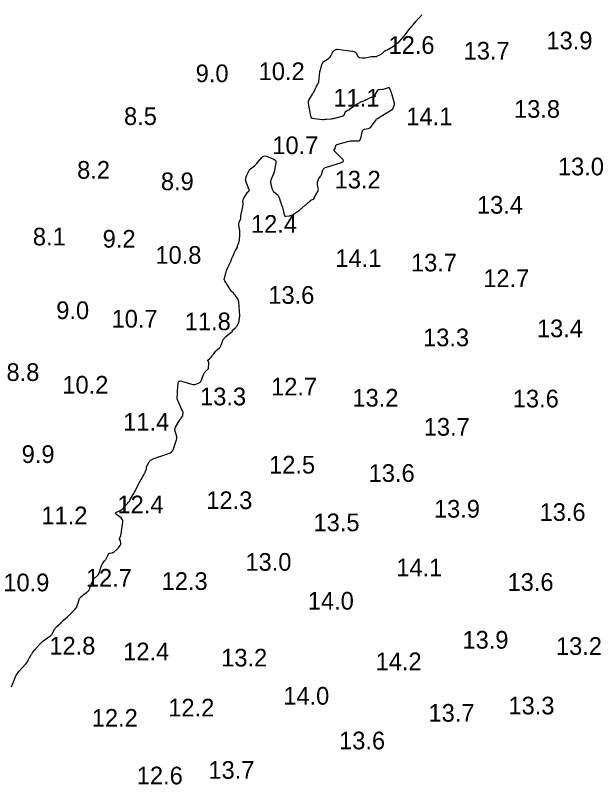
# Model space of a CAD drawing. Extents: x 815352 to 820877, y 582403 to 597439.
# Drawn here: x 820293.3 to 820456.5, y 589480.6 to 589698.1 of the extents above; entities that cross this region are included whole.
import ezdxf

# ---------------------------------------------------------------- set-up
doc = ezdxf.new("R2010")
doc.units = 0
doc.layers.add('V-CONT-EL12', color=7, linetype='Continuous')
doc.layers.add('V-TOPO-SOUN', color=7, linetype='Continuous')

msp = doc.modelspace()

# ---------------------------------------------------------------- linework, layer by layer
at = {"layer": 'V-CONT-EL12'}
msp.add_lwpolyline([(820292.15, 589508.3), (820293.31, 589511.15), (820293.5, 589511.58), (820293.73, 589511.98), (820294, 589512.36), (820294.31, 589512.72), (820296.14, 589514.7), (820296.19, 589514.75), (820296.24, 589514.8), (820296.28, 589514.86), (820296.33, 589514.91), (820296.5, 589515.13), (820296.54, 589515.19), (820296.58, 589515.25), (820296.61, 589515.31), (820296.64, 589515.37), (820296.94, 589516.02), (820297, 589516.14), (820297.07, 589516.27), (820297.14, 589516.39), (820297.21, 589516.52), (820297.73, 589517.36), (820297.85, 589517.54), (820297.97, 589517.72), (820298.09, 589517.89), (820298.22, 589518.06), (820298.77, 589518.77), (820298.91, 589518.94), (820299.05, 589519.11), (820299.19, 589519.28), (820299.34, 589519.44), (820300.16, 589520.35), (820300.23, 589520.42), (820300.3, 589520.49), (820300.37, 589520.56), (820300.45, 589520.63), (820300.74, 589520.91), (820300.82, 589520.98), (820300.89, 589521.04), (820300.97, 589521.1), (820301.05, 589521.16), (820303.03, 589522.58), (820303.25, 589522.76), (820303.45, 589522.96), (820303.62, 589523.19), (820303.77, 589523.44), (820304.4, 589524.66), (820304.49, 589524.82), (820304.59, 589524.96), (820304.71, 589525.1), (820304.84, 589525.23), (820305.52, 589525.83), (820305.59, 589525.89), (820305.66, 589525.95), (820305.73, 589526.01), (820305.8, 589526.07), (820306.08, 589526.31), (820306.15, 589526.37), (820306.22, 589526.43), (820306.28, 589526.49), (820306.34, 589526.56), (820306.6, 589526.84), (820306.66, 589526.91), (820306.72, 589526.98), (820306.79, 589527.04), (820306.86, 589527.11), (820307.97, 589528.11), (820308.17, 589528.29), (820308.38, 589528.48), (820308.58, 589528.68), (820308.78, 589528.87), (820309.83, 589529.91), (820309.9, 589529.98), (820309.96, 589530.05), (820310.03, 589530.12), (820310.09, 589530.19), (820310.39, 589530.52), (820310.42, 589530.57), (820310.46, 589530.62), (820310.49, 589530.67), (820310.52, 589530.72), (820310.62, 589530.93), (820310.64, 589530.99), (820310.66, 589531.04), (820310.68, 589531.1), (820310.7, 589531.15), (820311.41, 589533.23), (820311.47, 589533.37), (820311.55, 589533.5), (820311.64, 589533.62), (820311.75, 589533.72), (820312.23, 589534.1), (820312.35, 589534.2), (820312.47, 589534.29), (820312.6, 589534.39), (820312.72, 589534.48), (820313.33, 589534.93), (820313.4, 589534.99), (820313.48, 589535.05), (820313.55, 589535.11), (820313.62, 589535.17), (820313.9, 589535.43), (820313.97, 589535.5), (820314.03, 589535.57), (820314.07, 589535.65), (820314.11, 589535.73), (820314.27, 589536.13), (820314.31, 589536.22), (820314.35, 589536.32), (820314.39, 589536.41), (820314.42, 589536.51), (820315.02, 589538.11), (820315.13, 589538.36), (820315.27, 589538.6), (820315.44, 589538.82), (820315.64, 589539.02), (820316.49, 589539.77), (820316.69, 589539.97), (820316.85, 589540.19), (820316.98, 589540.43), (820317.08, 589540.7), (820317.65, 589542.63), (820317.71, 589542.81), (820317.79, 589542.98), (820317.89, 589543.14), (820318, 589543.29), (820318.5, 589543.89), (820318.61, 589544.03), (820318.71, 589544.17), (820318.81, 589544.33), (820318.89, 589544.48), (820319.32, 589545.27), (820319.36, 589545.35), (820319.4, 589545.43), (820319.44, 589545.51), (820319.48, 589545.59), (820319.63, 589545.92), (820319.67, 589545.99), (820319.73, 589546.05), (820319.8, 589546.08), (820319.88, 589546.1), (820320.56, 589546.18), (820320.7, 589546.21), (820320.83, 589546.25), (820320.95, 589546.32), (820321.07, 589546.4), (820321.95, 589547.15), (820322.09, 589547.27), (820322.21, 589547.4), (820322.34, 589547.53), (820322.45, 589547.66), (820322.95, 589548.29), (820323.03, 589548.41), (820323.07, 589548.52), (820323.09, 589548.65), (820323.09, 589548.78), (820322.99, 589549.46), (820322.97, 589549.53), (820322.95, 589549.6), (820322.92, 589549.67), (820322.89, 589549.74), (820322.73, 589550), (820322.7, 589550.06), (820322.69, 589550.13), (820322.7, 589550.2), (820322.72, 589550.26), (820322.95, 589550.68), (820323, 589550.77), (820323.04, 589550.87), (820323.07, 589550.97), (820323.09, 589551.07), (820323.22, 589551.73), (820323.24, 589551.88), (820323.27, 589552.02), (820323.29, 589552.17), (820323.31, 589552.32), (820323.64, 589554.86), (820323.64, 589555.22), (820323.56, 589555.54), (820323.39, 589555.82), (820323.13, 589556.06), (820321.84, 589557.02), (820321.65, 589557.2), (820321.59, 589557.38), (820321.67, 589557.54), (820321.89, 589557.69), (820323.04, 589558.26), (820323.32, 589558.42), (820323.58, 589558.6), (820323.82, 589558.81), (820324.04, 589559.04), (820324.97, 589560.1), (820325.19, 589560.37), (820325.39, 589560.64), (820325.58, 589560.92), (820325.76, 589561.22), (820326.56, 589562.65), (820326.73, 589562.95), (820326.89, 589563.24), (820327.05, 589563.54), (820327.21, 589563.84), (820327.83, 589565.04), (820327.99, 589565.34), (820328.15, 589565.64), (820328.31, 589565.93), (820328.47, 589566.23), (820329.7, 589568.41), (820329.78, 589568.56), (820329.86, 589568.71), (820329.93, 589568.86), (820329.99, 589569.02), (820330.27, 589569.77), (820330.3, 589569.87), (820330.33, 589569.97), (820330.35, 589570.08), (820330.37, 589570.18), (820330.44, 589570.61), (820330.46, 589570.71), (820330.49, 589570.81), (820330.53, 589570.91), (820330.58, 589571.01), (820331.08, 589571.86), (820331.17, 589572), (820331.29, 589572.13), (820331.42, 589572.25), (820331.57, 589572.34), (820332.26, 589572.73), (820332.38, 589572.8), (820332.51, 589572.86), (820332.64, 589572.91), (820332.78, 589572.96), (820333.32, 589573.14), (820333.45, 589573.19), (820333.59, 589573.23), (820333.72, 589573.28), (820333.86, 589573.32), (820337.15, 589574.47), (820337.23, 589574.5), (820337.31, 589574.55), (820337.38, 589574.61), (820337.44, 589574.69), (820337.67, 589574.99), (820337.73, 589575.07), (820337.78, 589575.16), (820337.82, 589575.24), (820337.85, 589575.33), (820338.8, 589578.09), (820338.83, 589578.16), (820338.85, 589578.24), (820338.87, 589578.32), (820338.88, 589578.39), (820338.94, 589578.71), (820338.95, 589578.79), (820338.95, 589578.87), (820338.94, 589578.94), (820338.92, 589579.02), (820338.43, 589580.61), (820338.37, 589580.9), (820338.37, 589581.18), (820338.44, 589581.45), (820338.56, 589581.71), (820339.79, 589583.74), (820339.87, 589583.87), (820339.95, 589584), (820340.03, 589584.13), (820340.12, 589584.25), (820340.52, 589584.83), (820340.57, 589584.92), (820340.61, 589585.02), (820340.64, 589585.12), (820340.66, 589585.23), (820340.7, 589585.66), (820340.71, 589585.77), (820340.7, 589585.88), (820340.67, 589585.98), (820340.63, 589586.08), (820339.18, 589589.25), (820339.11, 589589.45), (820339.05, 589589.66), (820339.03, 589589.87), (820339.02, 589590.09), (820339.07, 589590.98), (820339.09, 589591.2), (820339.1, 589591.42), (820339.12, 589591.64), (820339.13, 589591.86), (820339.29, 589594.1), (820339.38, 589594.48), (820339.56, 589594.71), (820339.84, 589594.8), (820340.22, 589594.75), (820343.4, 589593.81), (820343.63, 589593.76), (820343.86, 589593.75), (820344.08, 589593.78), (820344.3, 589593.85), (820345.19, 589594.2), (820345.39, 589594.31), (820345.56, 589594.45), (820345.7, 589594.62), (820345.8, 589594.83), (820346.54, 589596.76), (820346.6, 589596.9), (820346.67, 589597.02), (820346.75, 589597.14), (820346.84, 589597.25), (820347.36, 589597.8), (820347.41, 589597.84), (820347.45, 589597.89), (820347.5, 589597.93), (820347.55, 589597.97), (820347.75, 589598.13), (820347.79, 589598.17), (820347.82, 589598.22), (820347.84, 589598.27), (820347.85, 589598.33), (820347.95, 589599.99), (820347.95, 589600.06), (820347.93, 589600.12), (820347.91, 589600.18), (820347.86, 589600.24), (820347.67, 589600.45), (820347.64, 589600.51), (820347.63, 589600.56), (820347.64, 589600.61), (820347.68, 589600.65), (820348.24, 589601.14), (820348.33, 589601.23), (820348.42, 589601.32), (820348.51, 589601.42), (820348.6, 589601.52), (820348.93, 589601.92), (820349.01, 589602.02), (820349.09, 589602.12), (820349.17, 589602.22), (820349.25, 589602.32), (820349.95, 589603.19), (820350.06, 589603.32), (820350.18, 589603.45), (820350.31, 589603.57), (820350.44, 589603.68), (820350.98, 589604.12), (820351.11, 589604.24), (820351.21, 589604.37), (820351.3, 589604.51), (820351.36, 589604.67), (820351.79, 589605.96), (820351.84, 589606.09), (820351.9, 589606.21), (820351.97, 589606.34), (820352.04, 589606.45), (820352.37, 589606.91), (820352.46, 589607.03), (820352.55, 589607.13), (820352.65, 589607.23), (820352.75, 589607.32), (820354.59, 589608.79), (820354.62, 589608.82), (820354.64, 589608.85), (820354.66, 589608.88), (820354.67, 589608.92), (820354.69, 589609.08), (820354.7, 589609.12), (820354.72, 589609.15), (820354.74, 589609.18), (820354.77, 589609.21), (820355.58, 589609.91), (820355.71, 589610.04), (820355.83, 589610.18), (820355.94, 589610.33), (820356.03, 589610.5), (820356.44, 589611.36), (820356.47, 589611.46), (820356.5, 589611.55), (820356.53, 589611.65), (820356.54, 589611.74), (820356.59, 589612.21), (820356.6, 589612.27), (820356.6, 589612.34), (820356.61, 589612.4), (820356.61, 589612.46), (820356.63, 589612.77), (820356.64, 589612.8), (820356.64, 589612.83), (820356.65, 589612.87), (820356.67, 589612.9), (820356.73, 589613.02), (820356.74, 589613.05), (820356.75, 589613.08), (820356.75, 589613.12), (820356.75, 589613.15), (820356.43, 589617.12), (820356.39, 589617.38), (820356.32, 589617.62), (820356.22, 589617.85), (820356.09, 589618.06), (820355.39, 589619.04), (820355.28, 589619.18), (820355.17, 589619.32), (820355.05, 589619.45), (820354.93, 589619.58), (820354.33, 589620.19), (820354.26, 589620.26), (820354.19, 589620.35), (820354.12, 589620.43), (820354.06, 589620.53), (820353.84, 589620.9), (820353.78, 589620.99), (820353.72, 589621.08), (820353.67, 589621.18), (820353.61, 589621.27), (820353.15, 589622.04), (820353.06, 589622.17), (820352.98, 589622.31), (820352.89, 589622.45), (820352.81, 589622.58), (820352.46, 589623.12), (820352.39, 589623.26), (820352.35, 589623.4), (820352.35, 589623.55), (820352.37, 589623.71), (820352.91, 589625.74), (820352.96, 589625.91), (820353.02, 589626.07), (820353.08, 589626.24), (820353.15, 589626.4), (820353.47, 589627.06), (820353.54, 589627.2), (820353.61, 589627.35), (820353.68, 589627.49), (820353.75, 589627.64), (820354.04, 589628.23), (820354.11, 589628.38), (820354.17, 589628.52), (820354.23, 589628.66), (820354.29, 589628.81), (820354.5, 589629.4), (820354.55, 589629.55), (820354.61, 589629.69), (820354.67, 589629.84), (820354.73, 589629.98), (820355.13, 589630.95), (820355.21, 589631.13), (820355.3, 589631.31), (820355.39, 589631.48), (820355.49, 589631.66), (820356.06, 589632.59), (820356.08, 589632.64), (820356.1, 589632.68), (820356.11, 589632.73), (820356.11, 589632.79), (820356.11, 589633), (820356.11, 589633.05), (820356.12, 589633.1), (820356.13, 589633.15), (820356.15, 589633.2), (820356.51, 589634.18), (820356.57, 589634.36), (820356.62, 589634.54), (820356.65, 589634.72), (820356.67, 589634.91), (820356.73, 589635.78), (820356.74, 589635.95), (820356.74, 589636.11), (820356.74, 589636.28), (820356.74, 589636.45), (820356.71, 589637.12), (820356.7, 589637.29), (820356.69, 589637.45), (820356.67, 589637.62), (820356.64, 589637.79), (820356.47, 589638.84), (820356.45, 589639.05), (820356.46, 589639.26), (820356.5, 589639.46), (820356.56, 589639.66), (820356.99, 589640.74), (820357.01, 589640.8), (820357.02, 589640.87), (820357.03, 589640.93), (820357.02, 589641), (820357, 589641.26), (820356.99, 589641.32), (820356.99, 589641.39), (820357, 589641.45), (820357.01, 589641.52), (820357.56, 589644.02), (820357.6, 589644.22), (820357.62, 589644.42), (820357.64, 589644.63), (820357.64, 589644.83), (820357.62, 589645.66), (820357.63, 589645.87), (820357.67, 589646.06), (820357.73, 589646.25), (820357.83, 589646.43), (820358.82, 589647.99), (820358.87, 589648.07), (820358.93, 589648.14), (820358.99, 589648.21), (820359.06, 589648.28), (820359.33, 589648.55), (820359.39, 589648.62), (820359.42, 589648.69), (820359.42, 589648.77), (820359.4, 589648.86), (820358.44, 589651.3), (820358.4, 589651.42), (820358.38, 589651.54), (820358.38, 589651.66), (820358.4, 589651.79), (820358.5, 589652.29), (820358.52, 589652.42), (820358.56, 589652.54), (820358.6, 589652.66), (820358.65, 589652.78), (820359.16, 589653.95), (820359.27, 589654.17), (820359.41, 589654.38), (820359.57, 589654.57), (820359.76, 589654.73), (820360.85, 589655.61), (820361.09, 589655.82), (820361.32, 589656.04), (820361.54, 589656.27), (820361.75, 589656.51), (820362.94, 589657.96), (820363.22, 589658.22), (820363.53, 589658.36), (820363.87, 589658.39), (820364.24, 589658.29), (820366.33, 589657.44), (820366.66, 589657.25), (820366.87, 589657), (820366.96, 589656.69), (820366.94, 589656.32), (820366.56, 589654.47), (820366.5, 589654.18), (820366.42, 589653.9), (820366.33, 589653.62), (820366.23, 589653.34), (820365.61, 589651.8), (820365.59, 589651.75), (820365.57, 589651.7), (820365.55, 589651.64), (820365.53, 589651.59), (820365.44, 589651.34), (820365.42, 589651.31), (820365.42, 589651.28), (820365.41, 589651.24), (820365.41, 589651.21), (820365.4, 589651.07), (820365.4, 589651.04), (820365.41, 589651), (820365.41, 589650.97), (820365.41, 589650.93), (820365.52, 589650.39), (820365.54, 589650.29), (820365.56, 589650.19), (820365.59, 589650.09), (820365.61, 589649.99), (820365.87, 589648.98), (820365.94, 589648.78), (820366.03, 589648.61), (820366.15, 589648.45), (820366.3, 589648.31), (820367.29, 589647.52), (820367.34, 589647.48), (820367.39, 589647.43), (820367.43, 589647.38), (820367.47, 589647.32), (820367.61, 589647.09), (820367.64, 589647.04), (820367.67, 589646.98), (820367.7, 589646.91), (820367.72, 589646.85), (820368.32, 589645.13), (820368.37, 589645), (820368.41, 589644.87), (820368.46, 589644.74), (820368.51, 589644.61), (820368.71, 589644.11), (820368.76, 589643.98), (820368.8, 589643.85), (820368.84, 589643.72), (820368.87, 589643.58), (820369.28, 589641.72), (820369.35, 589641.52), (820369.47, 589641.39), (820369.63, 589641.33), (820369.84, 589641.33), (820370.77, 589641.47), (820370.99, 589641.51), (820371.21, 589641.58), (820371.42, 589641.68), (820371.62, 589641.79), (820373.58, 589643.11), (820373.79, 589643.25), (820374, 589643.4), (820374.2, 589643.56), (820374.4, 589643.73), (820375.23, 589644.45), (820375.39, 589644.59), (820375.55, 589644.73), (820375.71, 589644.88), (820375.87, 589645.02), (820376.63, 589645.73), (820376.72, 589645.81), (820376.82, 589645.88), (820376.92, 589645.93), (820377.03, 589645.98), (820377.62, 589646.2), (820377.66, 589646.22), (820377.7, 589646.25), (820377.72, 589646.29), (820377.73, 589646.34), (820377.76, 589646.56), (820377.77, 589646.61), (820377.78, 589646.67), (820377.8, 589646.72), (820377.83, 589646.76), (820378.75, 589648.3), (820378.86, 589648.52), (820378.92, 589648.74), (820378.94, 589648.97), (820378.91, 589649.21), (820378.7, 589650.31), (820378.68, 589650.49), (820378.68, 589650.66), (820378.7, 589650.83), (820378.73, 589651), (820378.95, 589651.75), (820379, 589651.88), (820379.06, 589652.01), (820379.13, 589652.13), (820379.22, 589652.25), (820379.58, 589652.69), (820379.67, 589652.8), (820379.74, 589652.93), (820379.8, 589653.05), (820379.85, 589653.19), (820380.25, 589654.46), (820380.35, 589654.69), (820380.5, 589654.88), (820380.69, 589655.03), (820380.93, 589655.13), (820385.45, 589656.51), (820385.86, 589656.71), (820386.05, 589656.95), (820386, 589657.26), (820385.72, 589657.62), (820383.45, 589659.85), (820383.41, 589659.91), (820383.39, 589659.97), (820383.4, 589660.03), (820383.43, 589660.1), (820383.61, 589660.38), (820383.65, 589660.45), (820383.68, 589660.52), (820383.71, 589660.59), (820383.73, 589660.67), (820383.89, 589661.28), (820383.93, 589661.4), (820384, 589661.49), (820384.09, 589661.57), (820384.2, 589661.61), (820387.24, 589662.48), (820387.58, 589662.57), (820387.93, 589662.63), (820388.28, 589662.66), (820388.63, 589662.66), (820390.06, 589662.63), (820390.38, 589662.67), (820390.63, 589662.8), (820390.8, 589663.01), (820390.91, 589663.32), (820391.3, 589665.25), (820391.38, 589665.5), (820391.52, 589665.69), (820391.71, 589665.84), (820391.96, 589665.93), (820393.05, 589666.2), (820393.31, 589666.28), (820393.55, 589666.41), (820393.76, 589666.58), (820393.94, 589666.78), (820395.33, 589668.64), (820395.42, 589668.75), (820395.52, 589668.85), (820395.63, 589668.94), (820395.74, 589669.02), (820396.38, 589669.41), (820396.42, 589669.43), (820396.46, 589669.46), (820396.5, 589669.49), (820396.54, 589669.53), (820396.69, 589669.66), (820396.73, 589669.69), (820396.77, 589669.72), (820396.81, 589669.75), (820396.85, 589669.78), (820399.89, 589671.59), (820399.92, 589671.61), (820399.94, 589671.63), (820399.96, 589671.65), (820399.97, 589671.67), (820400.03, 589671.78), (820400.04, 589671.81), (820400.05, 589671.84), (820400.06, 589671.87), (820400.07, 589671.9), (820400.45, 589672.97), (820400.46, 589673), (820400.47, 589673.02), (820400.47, 589673.05), (820400.48, 589673.08), (820400.48, 589673.19), (820400.48, 589673.22), (820400.48, 589673.25), (820400.48, 589673.27), (820400.47, 589673.3), (820399.69, 589676), (820399.64, 589676.18), (820399.58, 589676.36), (820399.52, 589676.54), (820399.45, 589676.72), (820399.19, 589677.44), (820399.11, 589677.59), (820399, 589677.67), (820398.86, 589677.7), (820398.7, 589677.67), (820397.27, 589677.15), (820397.26, 589677.14), (820397.24, 589677.14), (820397.23, 589677.15), (820397.21, 589677.16), (820397.15, 589677.19), (820397.14, 589677.2), (820397.12, 589677.21), (820397.1, 589677.21), (820397.09, 589677.21), (820396.07, 589677.11), (820395.9, 589677.08), (820395.76, 589677.01), (820395.64, 589676.91), (820395.54, 589676.77), (820395.02, 589675.87), (820394.99, 589675.81), (820394.96, 589675.74), (820394.96, 589675.67), (820394.96, 589675.6), (820394.98, 589675.31), (820394.98, 589675.24), (820394.96, 589675.18), (820394.92, 589675.14), (820394.86, 589675.1), (820394.48, 589674.92), (820394.42, 589674.9), (820394.37, 589674.89), (820394.31, 589674.89), (820394.26, 589674.89), (820394.02, 589674.92), (820393.96, 589674.93), (820393.91, 589674.92), (820393.85, 589674.91), (820393.8, 589674.89), (820392.31, 589674.17), (820392.17, 589674.1), (820392.02, 589674.04), (820391.88, 589673.98), (820391.73, 589673.93), (820391.12, 589673.73), (820390.98, 589673.68), (820390.83, 589673.61), (820390.69, 589673.54), (820390.55, 589673.46), (820389.94, 589673.08), (820389.83, 589673.01), (820389.72, 589672.94), (820389.62, 589672.87), (820389.51, 589672.8), (820389.1, 589672.51), (820388.99, 589672.44), (820388.89, 589672.37), (820388.79, 589672.29), (820388.68, 589672.22), (820387.76, 589671.52), (820387.69, 589671.47), (820387.62, 589671.42), (820387.54, 589671.38), (820387.46, 589671.35), (820387.14, 589671.22), (820387.07, 589671.19), (820386.99, 589671.14), (820386.92, 589671.1), (820386.86, 589671.04), (820386.52, 589670.76), (820386.45, 589670.69), (820386.39, 589670.61), (820386.35, 589670.52), (820386.31, 589670.43), (820386.15, 589669.92), (820386.1, 589669.82), (820386.04, 589669.73), (820385.95, 589669.67), (820385.84, 589669.63), (820383.59, 589669.02), (820383.34, 589668.96), (820383.1, 589668.91), (820382.85, 589668.87), (820382.59, 589668.84), (820381.28, 589668.72), (820381.18, 589668.71), (820381.08, 589668.7), (820380.98, 589668.69), (820380.88, 589668.68), (820380.47, 589668.63), (820380.37, 589668.63), (820380.27, 589668.62), (820380.17, 589668.63), (820380.07, 589668.63), (820377.78, 589668.86), (820377.4, 589668.95), (820377.12, 589669.12), (820376.91, 589669.4), (820376.79, 589669.76), (820376.14, 589673.18), (820376.11, 589673.52), (820376.14, 589673.85), (820376.23, 589674.16), (820376.39, 589674.46), (820377.3, 589675.89), (820377.42, 589676.07), (820377.52, 589676.26), (820377.62, 589676.44), (820377.72, 589676.64), (820378.12, 589677.48), (820378.2, 589677.64), (820378.28, 589677.79), (820378.36, 589677.94), (820378.45, 589678.09), (820378.81, 589678.69), (820378.9, 589678.84), (820378.96, 589679), (820379.01, 589679.17), (820379.04, 589679.34), (820379.38, 589682.16), (820379.38, 589682.19), (820379.39, 589682.21), (820379.39, 589682.24), (820379.4, 589682.27), (820379.43, 589682.38), (820379.43, 589682.4), (820379.44, 589682.43), (820379.44, 589682.45), (820379.45, 589682.47), (820379.48, 589682.57), (820379.48, 589682.59), (820379.49, 589682.62), (820379.5, 589682.64), (820379.51, 589682.66), (820379.96, 589684.28), (820380.05, 589684.54), (820380.19, 589684.77), (820380.37, 589684.97), (820380.59, 589685.15), (820381.82, 589685.96), (820382.02, 589686.11), (820382.2, 589686.28), (820382.36, 589686.48), (820382.49, 589686.7), (820383.17, 589687.98), (820383.19, 589688.02), (820383.22, 589688.06), (820383.25, 589688.09), (820383.28, 589688.12), (820383.43, 589688.24), (820383.46, 589688.26), (820383.5, 589688.29), (820383.54, 589688.31), (820383.58, 589688.33), (820383.98, 589688.51), (820384.06, 589688.54), (820384.14, 589688.56), (820384.23, 589688.56), (820384.31, 589688.56), (820388.37, 589688.07), (820388.46, 589688.06), (820388.55, 589688.04), (820388.63, 589688.02), (820388.72, 589688), (820389.09, 589687.89), (820389.16, 589687.87), (820389.22, 589687.84), (820389.28, 589687.8), (820389.33, 589687.76), (820389.54, 589687.58), (820389.59, 589687.53), (820389.64, 589687.48), (820389.68, 589687.42), (820389.71, 589687.36), (820390.15, 589686.55), (820390.24, 589686.41), (820390.36, 589686.31), (820390.5, 589686.24), (820390.67, 589686.21), (820391.46, 589686.13), (820391.65, 589686.12), (820391.84, 589686.12), (820392.03, 589686.14), (820392.21, 589686.17), (820393.89, 589686.52), (820394.02, 589686.55), (820394.15, 589686.56), (820394.27, 589686.56), (820394.4, 589686.56), (820395.11, 589686.51), (820395.15, 589686.51), (820395.18, 589686.51), (820395.21, 589686.51), (820395.25, 589686.51), (820395.38, 589686.53), (820395.41, 589686.53), (820395.44, 589686.54), (820395.47, 589686.55), (820395.5, 589686.57), (820396.37, 589687.02), (820396.52, 589687.11), (820396.67, 589687.2), (820396.81, 589687.3), (820396.95, 589687.41), (820397.73, 589688.09), (820397.8, 589688.15), (820397.88, 589688.2), (820397.96, 589688.24), (820398.05, 589688.27), (820398.41, 589688.39), (820398.5, 589688.43), (820398.58, 589688.46), (820398.66, 589688.51), (820398.75, 589688.55), (820400.68, 589689.72), (820400.74, 589689.77), (820400.8, 589689.82), (820400.85, 589689.87), (820400.89, 589689.93), (820401.08, 589690.21), (820401.12, 589690.26), (820401.16, 589690.3), (820401.21, 589690.33), (820401.27, 589690.35), (820401.53, 589690.42), (820401.59, 589690.44), (820401.64, 589690.47), (820401.69, 589690.51), (820401.74, 589690.55), (820403, 589692.03), (820403.21, 589692.28), (820403.41, 589692.53), (820403.61, 589692.78), (820403.81, 589693.04), (820404.81, 589694.43), (820404.88, 589694.52), (820404.96, 589694.61), (820405.03, 589694.7), (820405.11, 589694.79), (820405.43, 589695.12), (820405.51, 589695.21), (820405.59, 589695.29), (820405.66, 589695.38), (820405.74, 589695.47), (820406.51, 589696.43), (820406.67, 589696.62), (820406.83, 589696.8), (820406.99, 589696.99), (820407.16, 589697.16), (820407.88, 589697.91), (820408.05, 589698.1), (820408.21, 589698.3)], dxfattribs=at)

# ---------------------------------------------------------------- texts
at = {"layer": 'V-TOPO-SOUN'}
for s, p in [('12.6 ', (820398.78, 589687.26)), ('13.9 ', (820443.45, 589688.54)), ('13.7 ', (820420.03, 589685.65)), ('9.0', (820344.25, 589679.25)), ('10.2 ', (820362.06, 589679.84)), ('11.1 ', (820383.19, 589672.36)), ('13.8 ', (820434.27, 589669.18)), ('8.5', (820323.98, 589667.15)), ('14.1 ', (820403.83, 589667.08)), ('10.7 ', (820365.93, 589658.91)), ('13.0 ', (820446.7, 589652.91)), ('8.2', (820310.72, 589651.96)), ('8.9', (820334.41, 589648.71)), ('13.2 ', (820383.55, 589649.2)), ('13.4 ', (820423.8, 589642.08)), ('12.4 ', (820359.89, 589636.67)), ('8.1', (820298.2, 589633.09)), ('9.2', (820317.94, 589632.47)), ('10.8 ', (820332.86, 589627.91)), ('14.1 ', (820383.75, 589626.99)), ('13.7 ', (820405.13, 589625.74)), ('12.7 ', (820425.57, 589621.31)), ('13.6 ', (820364.79, 589616.59)), ('9.0', (820304.82, 589612.26)), ('10.7 ', (820320.46, 589609.86)), ('11.8 ', (820341.16, 589609.11)), ('13.4 ', (820440.76, 589607.14)), ('13.3 ', (820408.55, 589604.58)), ('8.8', (820290.74, 589594.77)), ('10.2 ', (820306.54, 589591.2)), ('12.7 ', (820365.57, 589590.67)), ('13.3 ', (820345.49, 589587.88)), ('13.2 ', (820388.57, 589587.52)), ('13.6 ', (820433.92, 589587.29)), ('11.4 ', (820323.74, 589580.73)), ('13.7 ', (820408.74, 589579.29)), ('9.9', (820295.04, 589571.58)), ('12.5 ', (820365.01, 589568.59)), ('13.6 ', (820393.17, 589566.23)), ('12.4 ', (820322.13, 589557.34)), ('12.3 ', (820347.26, 589558.55)), ('13.9 ', (820411.63, 589556.12)), ('13.6 ', (820441.5, 589555.2)), ('11.2 ', (820300.61, 589554.25)), ('13.5 ', (820377.57, 589552.28)), ('13.0 ', (820358.31, 589541.1)), ('14.1 ', (820400.97, 589539.52)), ('10.9 ', (820289.85, 589535.29)), ('12.7 ', (820313.2, 589536.6)), ('12.3 ', (820334.63, 589535.68)), ('13.6 ', (820432.44, 589535.42)), ('14.0 ', (820375.96, 589530.11)), ('13.9 ', (820419.7, 589519.08)), ('12.8 ', (820302.87, 589517.41)), ('12.4 ', (820323.74, 589515.77)), ('13.2 ', (820446.14, 589517.31)), ('13.2 ', (820351.46, 589514.03)), ('14.2 ', (820395.13, 589512.98)), ('14.0 ', (820369.01, 589503.24)), ('13.3 ', (820432.69, 589500.48)), ('12.2 ', (820336.5, 589499.89)), ('13.7 ', (820410.09, 589498.41)), ('12.2 ', (820314.85, 589497)), ('13.6 ', (820384.8, 589490.6)), ('12.6 ', (820327.59, 589480.7)), ('13.7 ', (820347.85, 589482.27))]:
    msp.add_text(s, height=5, dxfattribs=at).set_placement(p)

doc.saveas('drawing.dxf')
